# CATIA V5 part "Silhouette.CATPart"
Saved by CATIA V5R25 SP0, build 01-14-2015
Part number: Part1
Bounding box of the stored display mesh (mm): x -117 to 50, y -75 to 75, z 0 to 147
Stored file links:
  E:\cadcim\GSD_cat_v5-6r2014\Part_files\Silhouette.CATPart
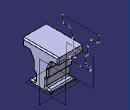
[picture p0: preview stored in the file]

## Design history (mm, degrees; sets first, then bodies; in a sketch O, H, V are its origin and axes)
Set1
  Sketch1 on yz-plane, origin (0, 0, 0), H (0, 1, 0), V (0, 0, 1)
    line L1 (0, 0) -> (45, 0)
    line L2 (45, 0) -> (45, 15)
    line L3 (45, 15) -> (22, 15)
    point P1 (45, 0)
    point P2 (45, 15)
    reference intersected line E1 through (0, 0) direction (0, 1) from zx-plane
    point P5 (0, 0)
    construction line L4 through (0, 0) direction (-1, 0)
    construction line L5 through (0, 0) direction (0, 1)
    point P6 (-45, 0)
    point P7 (-45, 15)
    line L6 (0, 0) -> (-45, 0)
    line L7 (-45, 0) -> (-45, 15)
    line L8 (-45, 15) -> (-22, 15)
    point P8 (-75, 147)
    line L9 (-75, 147) -> (75, 147)
    point P9 (75, 147)
    line L10 (75, 147) -> (75, 117)
    point P10 (75, 117)
    line L11 (75, 117) -> (45, 117)
    point P11 (45, 117)
    line L12 (45, 117) -> (30, 85)
    point P12 (30, 85)
    line L13 (30, 85) -> (30, 50)
    point P13 (30, 50)
    line L14 (30, 50) -> (22, 50)
    point P14 (22, 50)
    line L15 (22, 50) -> (22, 15)
    point P15 (22, 15)
    point P16 (-45, 15)
    point P17 (-75, 147)
    point P18 (-75, 117)
    point P19 (-45, 117)
    point P20 (-30, 85)
    point P21 (-30, 50)
    point P22 (-22, 50)
    point P23 (-22, 15)
    line L16 (-75, 147) -> (-75, 117)
    line L17 (-75, 117) -> (-45, 117)
    line L18 (-45, 117) -> (-30, 85)
    line L19 (-30, 85) -> (-30, 50)
    line L20 (-30, 50) -> (-22, 50)
    line L21 (-22, 50) -> (-22, 15)
    length L2 = 15
    length L10 = 30
    length L9 = 150
    length L11 = 30
    length L13 = 35
    length L15 = 35
    length L14 = 8
    distance P11 P12 V = 32
    distance P12 P11 H = 15
    horizontal: L1 H, L3 H, L9 H, L11 H, L14 H
    vertical: L2 V, L10 V, L13 V, L15 V
    symmetry: O P5 E1, H L4 E1, V L5 E1, P1 P6 E1, P2 P7 E1, L1 L6 E1, L2 L7 E1, L3 L8 E1, P2 P16 L5, P9 P17 L5, P10 P18 L5, P11 P19 L5, P12 P20 L5, P13 P21 L5, P14 P22 L5, P15 P23 L5, L10 L16 L5, L11 L17 L5, L12 L18 L5, L13 L19 L5, L14 L20 L5, L15 L21 L5, P9 P8 L5
    coincidence: P11 L2, O P5, P8 P17
Body1 (main body)
  Pad1: profile Sketch1, direction (1, 0, 0), length 50, mirrored extent
  Fillet1: radius 5, on edge [face of Pad1 from Sketch1.L10 | end face of Pad1]; edge [face of Pad1 from Sketch1.L16 | end face of Pad1]; edge [face of Pad1 from Sketch1.L17 | end face of Pad1]; edge [face of Pad1 from Sketch1.L18 | end face of Pad1]; edge [face of Pad1 from Sketch1.L19 | end face of Pad1]; edge [face of Pad1 from Sketch1.L20 | end face of Pad1]; edge [face of Pad1 from Sketch1.L21 | end face of Pad1]; edge [face of Pad1 from Sketch1.L8 | end face of Pad1]; edge [face of Pad1 from Sketch1.L3 | end face of Pad1]; edge [face of Pad1 from Sketch1.L15 | end face of Pad1]; edge [face of Pad1 from Sketch1.L14 | end face of Pad1]; end face of Pad1; edge [face of Pad1 from Sketch1.L10 | face of Pad1 from Sketch1.L11]; edge [face of Pad1 from Sketch1.L17 | face of Pad1 from Sketch1.L16]; edge [face of Pad1 from Sketch1.L11 | face of Pad1 from Sketch1.L12]; edge [face of Pad1 from Sketch1.L12 | face of Pad1 from Sketch1.L13]; edge [face of Pad1 from Sketch1.L13 | face of Pad1 from Sketch1.L14]; edge [face of Pad1 from Sketch1.L14 | face of Pad1 from Sketch1.L15]; edge [face of Pad1 from Sketch1.L15 | face of Pad1 from Sketch1.L3]; edge [face of Pad1 from Sketch1.L18 | face of Pad1 from Sketch1.L17]; edge [face of Pad1 from Sketch1.L19 | face of Pad1 from Sketch1.L18]; edge [face of Pad1 from Sketch1.L20 | face of Pad1 from Sketch1.L19]; edge [face of Pad1 from Sketch1.L21 | face of Pad1 from Sketch1.L20]; edge [face of Pad1 from Sketch1.L8 | face of Pad1 from Sketch1.L21]; face of Pad1 from Sketch1.L3; edge [face of Pad1 from Sketch1.L7 | face of Pad1 from Sketch1.L8]; edge [face of Pad1 from Sketch1.L2 | face of Pad1 from Sketch1.L1]; edge [face of Pad1 from Sketch1.L6 | face of Pad1 from Sketch1.L7]
  Plane1: type Offset, RefPlane start face of Pad1, Offset 67, reversed
  Silhouette1: Direction yz-plane, ShadowPlane Plane1, Support Fillet1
